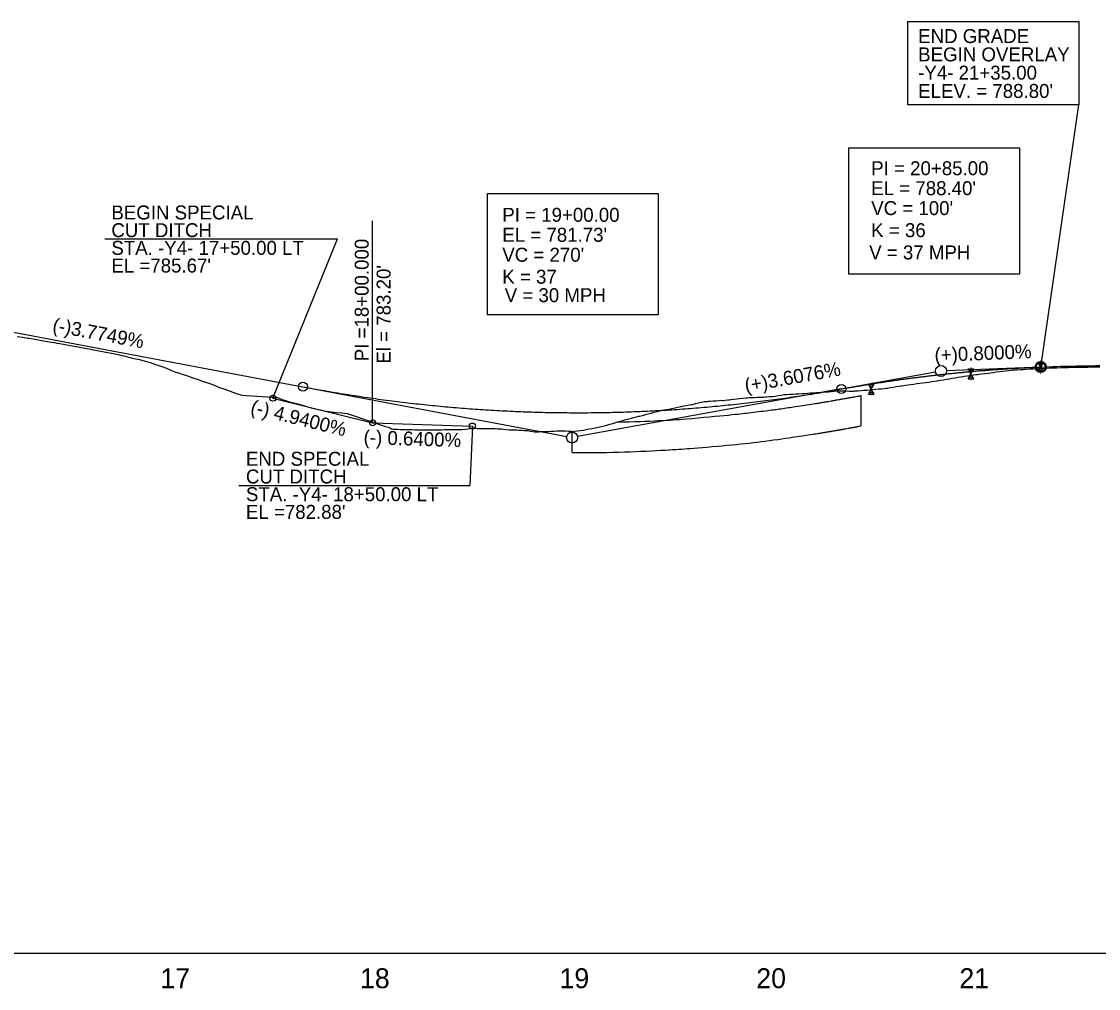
# Model space of a CAD drawing. Extents: x 579185 to 595036, y -53221 to -44640.
# Drawn here: x 583606 to 584146, y -49553 to -49068 of the extents above; entities that cross this region are included whole.
import ezdxf

# ---------------------------------------------------------------- set-up
doc = ezdxf.new("R2010")
doc.units = 0
for name, color, linetype in [('Exist Profile Cell', 7, 'Continuous'), ('Exist Vertical Profile Ground Line', 7, 'Continuous'), ('Exist Vertical Profile Horizontal Axis Label Major', 7, 'Continuous'), ('Old_Level_2', 7, 'Continuous'), ('Prop Grid Mask', 7, 'Continuous'), ('Prop Hatching', 7, 'Continuous'), ('Prop Vertical Profile Curve Label', 7, 'Continuous'), ('Prop Vertical Profile Ditch Grade Left', 7, 'Continuous'), ('Prop Vertical Profile Ditch Grade Left Label', 7, 'Continuous'), ('Prop Vertical Profile Grade', 7, 'Continuous'), ('Prop Vertical Profile Grade Label', 7, 'Continuous'), ('Prop VPI Ditch Grade Left Label', 7, 'Continuous'), ('Prop VPI Label', 7, 'Continuous')]:
    doc.layers.add(name, color=color, linetype=linetype)

msp = doc.modelspace()

# ---------------------------------------------------------------- linework, layer by layer
at = {"layer": 'Exist Profile Cell'}
msp.add_line((582981.74, -49535.12), (584272.59, -49535.12), dxfattribs=at)
at = {"layer": 'Exist Vertical Profile Ground Line'}
for points in [[(583603.5, -49225.8), (583606.17, -49226.2), (583608.84, -49226.59), (583609.41, -49226.67), (583611.51, -49227.03), (583614.18, -49227.49), (583616.84, -49227.95), (583619.51, -49228.41), (583622.18, -49228.86), (583623.39, -49229.07), (583624.85, -49229.34), (583627.52, -49229.82), (583630.19, -49230.3), (583632.86, -49230.78), (583633.41, -49230.89), (583635.53, -49231.27), (583638.2, -49231.76), (583640.34, -49232.15), (583640.86, -49232.25), (583643.53, -49232.79), (583646.2, -49233.32), (583648.87, -49233.86), (583651.54, -49234.39), (583654.21, -49234.92), (583655.88, -49235.26), (583656.88, -49235.49), (583659.55, -49236.13), (583662.22, -49236.78), (583664.88, -49237.42), (583667.72, -49238.11), (583670.22, -49238.91), (583672.89, -49239.77)], [(583672.89, -49239.77), (583673.48, -49239.96), (583675.56, -49240.7), (583678.35, -49241.71), (583680.9, -49242.8), (583682.59, -49243.53), (583683.57, -49243.83), (583684.38, -49244.09), (583686.23, -49244.71), (583688.9, -49245.61), (583691.57, -49246.51), (583694.24, -49247.41), (583694.56, -49247.52), (583696.91, -49248.33), (583699.58, -49249.26), (583701.41, -49249.9), (583702.25, -49250.24), (583704.92, -49251.35), (583707.59, -49252.28), (583710.25, -49253.22), (583712.92, -49254.16), (583715.59, -49255.08), (583716.53, -49255.2), (583718.26, -49255.33), (583720.93, -49255.52), (583723.6, -49255.71), (583726.27, -49255.89), (583728.94, -49256.06), (583731.61, -49256.23), (583733.97, -49256.37), (583734.27, -49256.49), (583736.94, -49257.49), (583738.54, -49258.09), (583739.61, -49258.36), (583742.28, -49259.05), (583744.95, -49259.74), (583747.62, -49260.54), (583750.31, -49261.34), (583752.99, -49262.1), (583755.63, -49262.66), (583758.29, -49263.22), (583759.55, -49263.48), (583760.96, -49263.61), (583763.63, -49263.86), (583766.3, -49264.11), (583768.97, -49264.41), (583770.45, -49264.92), (583771.93, -49265.43), (583773.41, -49265.93), (583774.89, -49266.44), (583776.37, -49266.94), (583777.85, -49267.45), (583779.33, -49267.95), (583780.81, -49268.46), (583782.29, -49268.96), (583783.77, -49269.46), (583785.25, -49269.96), (583786.73, -49270.46), (583787.34, -49270.67), (583788.21, -49270.91), (583789.7, -49271.32), (583790.16, -49271.51), (583791.22, -49272.12), (583791.66, -49272.26), (583792.65, -49272.29), (583794.13, -49272.33), (583795.61, -49272.37), (583797.09, -49272.41), (583798.57, -49272.45), (583800.05, -49272.48), (583801.53, -49272.52), (583803.01, -49272.55), (583803.59, -49272.56), (583804.49, -49272.56), (583805.97, -49272.57), (583807.45, -49272.58), (583808.93, -49272.58), (583810.41, -49272.58), (583811.89, -49272.57), (583813.37, -49272.56), (583814.85, -49272.55), (583816.33, -49272.54), (583817.81, -49272.53), (583819.29, -49272.51), (583820.77, -49272.49), (583822.26, -49272.46), (583823.74, -49272.44), (583825.22, -49272.41), (583826.7, -49272.38), (583828.22, -49272.34), (583829.66, -49272.08), (583831.14, -49271.82), (583832.62, -49271.85), (583834.1, -49271.88), (583835.58, -49271.91), (583837.06, -49271.93), (583838.54, -49271.95), (583840.2, -49271.98), (583841.5, -49271.94), (583842.98, -49271.99), (583844.46, -49272.05)], [(583967.31, -49256.78), (583968.79, -49256.6), (583969.59, -49256.51), (583970.27, -49256.47), (583971.75, -49256.38), (583972.33, -49256.35), (583973.23, -49256.32), (583974.71, -49256.27), (583975.04, -49256.26), (583976.19, -49256.22), (583977.67, -49256.16), (583978.81, -49256.11), (583979.15, -49256.08), (583980.63, -49255.98), (583982.11, -49255.88), (583982.56, -49255.84), (583983.59, -49255.67), (583985.07, -49255.41), (583986.55, -49255.15), (583988.03, -49254.91), (583989.51, -49254.84), (583990.99, -49254.76), (583992.47, -49254.68), (583993.95, -49254.6), (583995.43, -49254.52), (583996.91, -49254.43), (583998.39, -49254.34), (583999.87, -49254.24), (584001.35, -49254.14), (584002.83, -49254.04), (584004.31, -49253.93), (584005.79, -49253.83), (584007.28, -49253.71), (584008.76, -49253.6), (584010.24, -49253.48), (584011.72, -49253.36), (584013.2, -49253.24), (584014.68, -49253.11), (584015.81, -49253.01), (584016.16, -49253.02), (584017.64, -49253.08), (584019.12, -49253.14), (584020.6, -49253.19), (584022.21, -49253.25), (584023, -49253.15), (584023.56, -49253.13), (584024.48, -49253.09), (584025.04, -49253.05), (584026.52, -49252.92), (584028, -49252.79), (584029.48, -49252.66), (584030.96, -49252.53), (584032.44, -49252.4), (584033.92, -49252.26), (584035.4, -49252.13), (584036.88, -49251.98), (584038.36, -49251.83), (584039.48, -49251.72), (584039.84, -49251.66), (584040.59, -49251.54), (584041.32, -49251.42), (584042.8, -49251.19), (584044.28, -49250.95), (584045.76, -49250.72), (584046.83, -49250.55), (584047.24, -49250.49), (584048.72, -49250.28), (584050.2, -49250.08), (584051.68, -49249.87), (584053.16, -49249.66), (584054.64, -49249.46), (584056.12, -49249.25), (584057.6, -49249.04), (584059.08, -49248.84), (584060.56, -49248.63), (584062.04, -49248.42), (584063.52, -49248.21), (584065, -49248.01), (584065.4, -49247.95), (584066.48, -49247.77), (584067.96, -49247.52), (584069.44, -49247.27), (584070.92, -49247.02), (584072.4, -49246.78), (584073.88, -49246.53), (584075.36, -49246.28), (584076.84, -49246.03), (584078.32, -49245.78), (584079.8, -49245.54), (584081.29, -49245.29), (584082.22, -49245.19), (584083.02, -49245.11), (584084.24, -49244.94), (584085.02, -49244.84), (584085.72, -49244.75), (584087.2, -49244.56), (584088.68, -49244.37), (584090.16, -49244.18), (584091.64, -49243.99), (584093.12, -49243.8), (584094.6, -49243.61)], [(584094.6, -49243.61), (584096.08, -49243.42), (584097.56, -49243.24), (584099.04, -49243.05), (584100.53, -49242.87), (584102.01, -49242.69), (584103.06, -49242.56), (584103.49, -49242.54), (584104.97, -49242.45), (584106.45, -49242.37), (584107.93, -49242.29), (584109.41, -49242.21), (584111.34, -49242.1), (584113.27, -49242), (584115.2, -49241.89), (584117.13, -49241.79), (584119.06, -49241.68), (584120.99, -49241.58), (584122.92, -49241.48), (584124.85, -49241.44), (584126.78, -49241.39), (584128.71, -49241.35), (584130.64, -49241.31), (584132.57, -49241.27), (584134.7, -49241.22), (584136.43, -49241.19), (584138.36, -49241.15), (584140.29, -49241.11), (584142.22, -49241.07), (584144.15, -49241.04), (584146.34, -49241)], [(583844.46, -49272.05), (583845.94, -49272.09), (583846.41, -49272.11), (583847.42, -49272.23), (583848.9, -49272.39), (583850.38, -49272.55), (583850.99, -49272.61), (583851.86, -49272.69), (583853.34, -49272.69), (583854.09, -49272.68), (583854.82, -49272.73), (583856.3, -49272.81), (583857.78, -49272.9), (583859.55, -49272.99), (583860.74, -49273.23), (583862.22, -49273.53), (583862.93, -49273.67), (583863.7, -49273.66), (583865.18, -49273.56), (583865.88, -49273.51), (583866.66, -49273.49), (583868.14, -49273.44), (583869.83, -49273.38), (583871.1, -49273.31), (583872.78, -49273.21), (583874.06, -49273.19), (583875.54, -49273.18), (583877.02, -49273.16), (583877.66, -49273.15), (583878.5, -49273.19), (583879.98, -49273.26), (583881.46, -49273.33), (583882.28, -49273.37), (583882.94, -49273.3), (583884.42, -49273.16), (583886, -49273), (583887.38, -49272.74), (583888.86, -49272.45), (583890.34, -49272.17), (583891.82, -49271.88), (583893.3, -49271.6), (583894.78, -49271.31), (583896.26, -49271.02), (583897.87, -49270.69), (583899.22, -49270.28), (583900.7, -49269.84), (583902.18, -49269.39), (583903.66, -49268.94), (583905.14, -49268.49), (583906.62, -49268.04), (583907.73, -49267.71), (583908.1, -49267.61), (583909.58, -49267.23), (583911.06, -49266.85), (583912.54, -49266.46), (583914.03, -49266.08), (583915.14, -49265.83), (583915.62, -49265.69), (583916.99, -49265.35), (583918.47, -49264.97), (583919.95, -49264.59), (583921.43, -49264.21), (583922.91, -49263.83), (583924.39, -49263.44), (583925.87, -49263.06), (583926.73, -49262.83), (583927.35, -49262.74), (583928.83, -49262.5), (583930.31, -49262.25), (583931.79, -49261.93), (583933.27, -49261.6), (583934.75, -49261.28), (583936.23, -49260.95), (583936.63, -49260.86), (583937.71, -49260.66), (583939.19, -49260.39), (583940.67, -49260.13), (583941.83, -49259.91), (583942.15, -49259.83), (583943.63, -49259.45), (583945.11, -49259.08), (583946.59, -49258.69), (583947.29, -49258.51), (583948.07, -49258.46), (583949.55, -49258.34), (583950.18, -49258.29), (583951.03, -49258.23), (583952.51, -49258.12), (583953.99, -49258), (583955.47, -49257.88), (583956.33, -49257.81), (583956.95, -49257.83), (583957.71, -49257.84), (583958.43, -49257.77), (583959.91, -49257.6), (583960.56, -49257.53), (583961.39, -49257.44), (583962.87, -49257.28), (583964.35, -49257.12), (583965.83, -49256.95), (583967.31, -49256.78)]]:
    msp.add_lwpolyline(points, dxfattribs=at)
at = {"layer": 'Old_Level_2'}
for p, q in [((584116.74, -49241.11), (584115.3, -49238.61)), ((584115.3, -49238.61), (584118.19, -49238.61)), ((584115.78, -49239.44), (584117.71, -49239.44)), ((584116.74, -49241.11), (584118.19, -49238.61)), ((584081.74, -49244.6), (584080.3, -49242.1)), ((584080.3, -49242.1), (584083.19, -49242.1)), ((584080.3, -49247.1), (584081.74, -49244.6)), ((584080.78, -49242.93), (584082.71, -49242.93)), ((584081.26, -49243.76), (584082.23, -49243.76)), ((584081.74, -49244.6), (584083.19, -49242.1)), ((584083.19, -49247.1), (584081.74, -49244.6)), ((584115.3, -49243.61), (584116.74, -49241.11)), ((584115.3, -49243.61), (584118.19, -49243.61)), ((584115.78, -49242.78), (584117.71, -49242.78)), ((584116.26, -49240.28), (584117.23, -49240.28)), ((584116.26, -49241.95), (584117.23, -49241.95)), ((584118.19, -49243.61), (584116.74, -49241.11)), ((584031.74, -49252.21), (584030.3, -49249.71)), ((584030.3, -49249.71), (584033.19, -49249.71)), ((584031.75, -49252.21), (584033.19, -49249.71)), ((584080.3, -49247.1), (584083.19, -49247.1)), ((584080.78, -49246.26), (584082.71, -49246.26)), ((584081.26, -49245.43), (584082.23, -49245.43)), ((584030.3, -49254.71), (584031.75, -49252.21)), ((584030.3, -49254.71), (584033.19, -49254.71)), ((584030.78, -49250.54), (584032.71, -49250.54)), ((584030.78, -49253.87), (584032.71, -49253.87)), ((584031.26, -49251.37), (584032.23, -49251.37)), ((584031.26, -49253.04), (584032.23, -49253.04)), ((584033.19, -49254.71), (584031.74, -49252.21))]:
    msp.add_line(p, q, dxfattribs=at)
at = {"layer": 'Prop Grid Mask'}
for points in [[(584050.09, -49067.86), (584135.87, -49067.86), (584135.87, -49109.69), (584050.09, -49109.69)], [(584020.56, -49131.28), (584106.12, -49131.28), (584106.12, -49194.51), (584020.56, -49194.51)], [(583839.26, -49154.1), (583924.83, -49154.1), (583924.83, -49214.93), (583839.26, -49214.93)]]:
    msp.add_lwpolyline(points, close=True, dxfattribs=at)
at = {"layer": 'Prop Hatching'}
for p, q in [((584026.74, -49270.57), (584026.74, -49255.47)), ((584017.61, -49257.05), (584017.63, -49257.05)), ((584020.22, -49271.83), (584020.27, -49271.82)), ((583881.74, -49284.02), (583881.74, -49273.34))]:
    msp.add_line(p, q, dxfattribs=at)
for points in [[(584017.63, -49257.05), (584018.25, -49256.94), (584018.88, -49256.83), (584019.91, -49256.64), (584020.31, -49256.57), (584021.12, -49256.43), (584021.53, -49256.36), (584022.69, -49256.16), (584023.44, -49256.03), (584025.05, -49255.75), (584025.9, -49255.61), (584026.74, -49255.47)], [(583904.22, -49268.77), (583921.68, -49268.31), (583939.13, -49267.23), (583963.01, -49264.91), (583969.49, -49264.19), (583980.92, -49262.77), (583985.87, -49262.11), (583994.48, -49260.87), (583998.15, -49260.32), (584003.22, -49259.51), (584004.64, -49259.28), (584007.01, -49258.89), (584007.97, -49258.73), (584009.9, -49258.41), (584010.87, -49258.24), (584012.4, -49257.98), (584012.94, -49257.88), (584014.03, -49257.69), (584014.58, -49257.59), (584015.95, -49257.35), (584016.78, -49257.2), (584017.61, -49257.05)], [(583881.74, -49284.02), (583896.25, -49284.08), (583910.76, -49283.72), (583932.83, -49282.53), (583940.4, -49282.01), (583963.1, -49280.1), (583978.18, -49278.38), (583996.03, -49275.8), (583998.85, -49275.38), (584003.65, -49274.63), (584005.62, -49274.32), (584008.09, -49273.91), (584008.59, -49273.83), (584009.57, -49273.67), (584010.05, -49273.59), (584011.03, -49273.43), (584011.53, -49273.34), (584012.56, -49273.17), (584013.09, -49273.08), (584013.91, -49272.94), (584014.2, -49272.89), (584014.64, -49272.81), (584014.79, -49272.78), (584015.08, -49272.73), (584015.22, -49272.71), (584015.5, -49272.66), (584015.64, -49272.64), (584016.06, -49272.56), (584016.34, -49272.51), (584017.19, -49272.36), (584017.75, -49272.26), (584018.95, -49272.05), (584019.59, -49271.94), (584020.22, -49271.83)], [(584020.27, -49271.82), (584020.47, -49271.78), (584020.68, -49271.74), (584021.3, -49271.63), (584021.72, -49271.56), (584022.25, -49271.46), (584022.37, -49271.44), (584022.82, -49271.36), (584023.17, -49271.3), (584023.57, -49271.23), (584023.63, -49271.22), (584023.79, -49271.19), (584023.89, -49271.17), (584024.05, -49271.15), (584024.09, -49271.14), (584024.17, -49271.12), (584024.24, -49271.11), (584024.49, -49271.06), (584024.68, -49271.02), (584025.45, -49270.85), (584025.97, -49270.74), (584026.74, -49270.57)]]:
    msp.add_open_spline(points, degree=3, dxfattribs=at)
at = {"layer": 'Prop Vertical Profile Curve Label'}
msp.add_line((584116.74, -49241.11), (584135.87, -49109.69), dxfattribs=at)
for centre in [(584116.74, -49241.11), (583746.74, -49251), (584016.74, -49252.13), (584016.74, -49252.13)]:
    msp.add_circle(centre, 2.25, dxfattribs=at)
at = {"layer": 'Prop Vertical Profile Ditch Grade Left'}
msp.add_lwpolyline([(583731.74, -49256.77), (583781.74, -49269.12), (583831.74, -49270.72)], dxfattribs=at)
at = {"layer": 'Prop Vertical Profile Ditch Grade Left Label'}
for p, q in [((583781.74, -49269.12), (583781.74, -49167.79)), ((583647.36, -49176.76), (583764.09, -49176.76)), ((583731.74, -49256.77), (583764.09, -49176.76)), ((583831.74, -49270.72), (583830.44, -49300.52)), ((583714.66, -49300.52), (583830.44, -49300.52))]:
    msp.add_line(p, q, dxfattribs=at)
for centre in [(583731.74, -49256.77), (583781.74, -49269.12), (583831.74, -49270.72)]:
    msp.add_circle(centre, 1.5, dxfattribs=at)
at = {"layer": 'Prop Vertical Profile Grade'}
msp.add_line((583581.74, -49219.86), (583746.74, -49251), dxfattribs=at)
msp.add_lwpolyline([(584116.74, -49241.17), (584122.89, -49240.85), (584124.83, -49240.81), (584126.76, -49240.77), (584128.69, -49240.73), (584130.63, -49240.68), (584132.56, -49240.64), (584134.69, -49240.59), (584136.42, -49240.56), (584138.35, -49240.52), (584140.28, -49240.49), (584142.21, -49240.45), (584144.14, -49240.41), (584146.33, -49240.37)], dxfattribs=at)
for points in [[(584016.74, -49252.13), (584018.74, -49251.77), (584020.74, -49251.42), (584022.74, -49251.07), (584024.74, -49250.73), (584026.74, -49250.4), (584028.74, -49250.07), (584030.74, -49249.74), (584032.74, -49249.42), (584034.74, -49249.11), (584036.74, -49248.8), (584038.74, -49248.5), (584040.74, -49248.21), (584042.74, -49247.91), (584044.74, -49247.63), (584046.74, -49247.35), (584048.74, -49247.08), (584050.74, -49246.81), (584052.74, -49246.55), (584054.74, -49246.29), (584056.74, -49246.04), (584058.74, -49245.79), (584060.74, -49245.55), (584062.74, -49245.32), (584064.74, -49245.09), (584066.74, -49244.87), (584068.74, -49244.65), (584070.74, -49244.44), (584072.74, -49244.23), (584074.74, -49244.03), (584076.74, -49243.83), (584078.74, -49243.64), (584080.74, -49243.46), (584082.74, -49243.28), (584084.74, -49243.11), (584086.74, -49242.94), (584088.74, -49242.78), (584090.74, -49242.63), (584092.74, -49242.48), (584094.74, -49242.33), (584096.74, -49242.19), (584098.74, -49242.06), (584100.74, -49241.93), (584102.74, -49241.81), (584104.74, -49241.69), (584106.74, -49241.58), (584108.74, -49241.48), (584110.74, -49241.38), (584112.74, -49241.28), (584114.74, -49241.19), (584116.74, -49241.11)], [(583746.74, -49251), (583752.14, -49252), (583757.54, -49252.96), (583762.94, -49253.88), (583768.34, -49254.76), (583773.74, -49255.6), (583779.14, -49256.4), (583784.54, -49257.16), (583789.94, -49257.88), (583795.34, -49258.56), (583800.74, -49259.2), (583806.14, -49259.8), (583811.54, -49260.36), (583816.94, -49260.88), (583822.34, -49261.36), (583827.74, -49261.8), (583833.14, -49262.21), (583838.54, -49262.57), (583843.94, -49262.89), (583849.34, -49263.17), (583854.74, -49263.41), (583860.14, -49263.61), (583865.54, -49263.78), (583870.94, -49263.9), (583876.34, -49263.98), (583881.74, -49264.02), (583887.14, -49264.03), (583892.54, -49263.99), (583897.94, -49263.91), (583903.34, -49263.79), (583908.74, -49263.64), (583914.14, -49263.44), (583919.54, -49263.2), (583924.94, -49262.93), (583930.34, -49262.61), (583935.74, -49262.26), (583941.14, -49261.86), (583946.54, -49261.42), (583951.94, -49260.95), (583957.34, -49260.43), (583962.74, -49259.88), (583968.14, -49259.28), (583973.54, -49258.65), (583978.94, -49257.97), (583984.34, -49257.26), (583989.74, -49256.5), (583995.14, -49255.71), (584000.54, -49254.87), (584005.94, -49254), (584011.34, -49253.08), (584016.74, -49252.13)]]:
    msp.add_spline(points, degree=3, dxfattribs=at)
at = {"layer": 'Prop VPI Label'}
for p, q in [((584016.74, -49252.13), (584064.04, -49243.6)), ((584116.74, -49241.11), (584069.49, -49243)), ((583746.74, -49251), (583879.04, -49275.97)), ((584016.74, -49252.13), (583884.45, -49275.99))]:
    msp.add_line(p, q, dxfattribs=at)
for centre in [(584116.74, -49241.11), (584066.74, -49243.11), (583881.74, -49276.48)]:
    msp.add_circle(centre, 2.75, dxfattribs=at)

# ---------------------------------------------------------------- texts
at = {"layer": 'Exist Vertical Profile Horizontal Axis Label Major'}
for s, p in [('17', (583675.28, -49552.62)), ('18', (583775.41, -49552.62)), ('19', (583875.45, -49552.62)), ('20', (583974.13, -49552.62)), ('21', (584075.97, -49552.62))]:
    msp.add_text(s, height=10, dxfattribs=at).set_placement(p)
at = {"layer": 'Old_Level_2'}
for p in [(584116.51, -49238.45), (584081.51, -49241.94), (584116.32, -49244.62), (584031.51, -49249.55), (584081.32, -49248.1), (584031.32, -49255.71)]:
    msp.add_text('6"', height=0.8, dxfattribs=at).set_placement(p)
at = {"layer": 'Prop Vertical Profile Curve Label'}
for s, p in [("VC = 100'", (584031.74, -49164.93)), ('K = 36', (584031.74, -49175.98)), ('V = 37 MPH', (584030.72, -49187.15)), ("VC = 270'", (583846.74, -49188.3)), ('K = 37', (583846.74, -49199.35)), ('V = 30 MPH', (583847.96, -49208.59))]:
    msp.add_text(s, height=7, dxfattribs=at).set_placement(p)
at = {"layer": 'Prop Vertical Profile Ditch Grade Left Label'}
for s, p in [('BEGIN SPECIAL', (583650.71, -49167.12)), ('CUT DITCH', (583650.71, -49175.99)), ('STA. -Y4- 17+50.00 LT ', (583650.71, -49184.86)), ("EL =785.67'", (583650.71, -49193.74)), ('END SPECIAL', (583718.19, -49290.64)), ('CUT DITCH', (583718.19, -49299.52)), ('STA. -Y4- 18+50.00 LT ', (583718.19, -49308.39)), ("EL =782.88'", (583718.19, -49317.27))]:
    msp.add_text(s, height=7, dxfattribs=at).set_placement(p)
for s, rotation, p in [('(-) 4.9400%', 346.1256, (583720.05, -49264.26)), ('(-) 0.6400%', 358.1672, (583777.11, -49279.75))]:
    msp.add_text(s, height=7, rotation=rotation, dxfattribs=at).set_placement(p)
at = {"layer": 'Prop Vertical Profile Grade Label'}
for s, rotation, p in [('(-)3.7749%', 349.3114, (583620.83, -49223.27)), ('(+)0.8000%', 2.2906, (584063.62, -49238.61)), ('(+)3.6076%', 10.225, (583968.96, -49253.9))]:
    msp.add_text(s, height=7, rotation=rotation, dxfattribs=at).set_placement(p)
at = {"layer": 'Prop VPI Ditch Grade Left Label'}
for s, p in [('PI =18+00.000', (583779.74, -49238.22)), ("El = 783.20'", (583790.74, -49239.4))]:
    msp.add_text(s, height=7, rotation=90, dxfattribs=at).set_placement(p)
at = {"layer": 'Prop VPI Label'}
for s, p in [('END GRADE', (584055.28, -49078.65)), ('BEGIN OVERLAY', (584055.28, -49087.83)), ('-Y4- 21+35.00', (584055.28, -49097)), ("ELEV. = 788.80'", (584055.28, -49106.18)), ('PI = 20+85.00', (584031.74, -49144.93)), ("EL = 788.40'", (584031.74, -49154.93)), ('PI = 19+00.00', (583846.74, -49168.3)), ("EL = 781.73'", (583846.74, -49178.3))]:
    msp.add_text(s, height=7, dxfattribs=at).set_placement(p)

doc.saveas('drawing.dxf')
